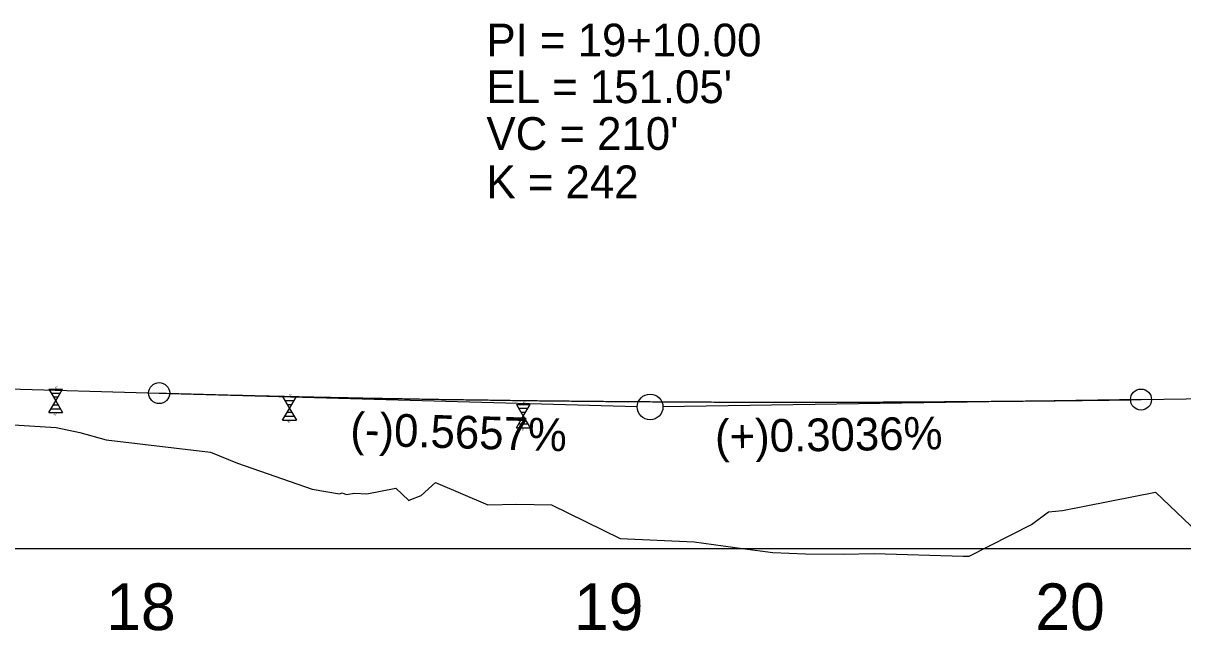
# Model space of a CAD drawing. Extents: x 573468 to 580768, y -57414 to -51768.
# Drawn here: x 574547.3 to 574795.4, y -53423 to -53293 of the extents above; entities that cross this region are included whole.
import ezdxf

# ---------------------------------------------------------------- set-up
doc = ezdxf.new("R2010")
doc.units = 0
for name, color, linetype in [('Exist Profile Cell', 7, 'Continuous'), ('Exist Vertical Profile Ground Line', 7, 'Continuous'), ('Exist Vertical Profile Horizontal Axis Label Major', 7, 'Continuous'), ('Pattern 2', 7, 'Continuous'), ('Prop Vertical Profile Curve Label', 7, 'Continuous'), ('Prop Vertical Profile Grade', 7, 'Continuous'), ('Prop Vertical Profile Grade Label', 7, 'Continuous'), ('Prop VPI Label', 7, 'Continuous')]:
    doc.layers.add(name, color=color, linetype=linetype)

msp = doc.modelspace()

# ---------------------------------------------------------------- linework, layer by layer
at = {"layer": 'Exist Profile Cell'}
msp.add_line((573502.62, -53405.32), (576177.52, -53405.32), dxfattribs=at)
at = {"layer": 'Exist Vertical Profile Ground Line'}
msp.add_lwpolyline([(574531.52, -53378.06), (574554.39, -53379.46), (574559.46, -53380.53), (574565.08, -53382.11), (574587.44, -53384.78), (574593.19, -53387.09), (574609.15, -53392.68), (574615.02, -53393.64), (574615.59, -53393.47), (574616.45, -53393.81), (574618.21, -53393.48), (574620.85, -53393.66), (574627.02, -53392.48), (574629.8, -53395.11), (574630.24, -53394.84), (574632.47, -53394.03), (574635.5, -53391.2), (574646.72, -53396.01), (574652.93, -53395.84), (574660.31, -53396.04), (574675.02, -53403.22), (574690.88, -53403.93), (574701.16, -53405.32), (574707.66, -53406.18), (574714.67, -53406.52), (574722.69, -53406.53), (574729.36, -53406.39), (574748.38, -53406.97), (574749.67, -53406.96), (574763.03, -53400.24), (574766.62, -53397.54), (574769.61, -53397.2), (574789.52, -53393.31), (574798.57, -53401.9)], dxfattribs=at)
at = {"layer": 'Pattern 2'}
for p, q in [((574552.84, -53371.27), (574555.77, -53371.27)), ((574552.84, -53371.27), (574554.31, -53373.77)), ((574553.33, -53372.1), (574555.29, -53372.1)), ((574553.82, -53372.94), (574554.8, -53372.94)), ((574554.31, -53373.77), (574555.77, -53371.27)), ((574602.84, -53372.87), (574605.77, -53372.87)), ((574602.84, -53372.87), (574604.31, -53375.37)), ((574603.33, -53373.7), (574605.29, -53373.7)), ((574604.31, -53375.37), (574605.77, -53372.87)), ((574552.84, -53376.27), (574554.31, -53373.77)), ((574553.33, -53375.44), (574555.29, -53375.44)), ((574553.82, -53374.6), (574554.8, -53374.6)), ((574554.31, -53373.77), (574555.77, -53376.27)), ((574602.84, -53377.87), (574604.31, -53375.37)), ((574603.82, -53374.54), (574604.8, -53374.54)), ((574603.82, -53376.2), (574604.8, -53376.2)), ((574604.31, -53375.37), (574605.77, -53377.87)), ((574652.84, -53374.52), (574655.77, -53374.52)), ((574652.84, -53374.52), (574654.31, -53377.02)), ((574653.33, -53375.35), (574655.29, -53375.35)), ((574653.82, -53376.19), (574654.8, -53376.19)), ((574654.31, -53377.02), (574655.77, -53374.52)), ((574552.84, -53376.27), (574555.77, -53376.27)), ((574602.84, -53377.87), (574605.77, -53377.87)), ((574603.33, -53377.04), (574605.29, -53377.04)), ((574652.84, -53379.52), (574654.31, -53377.02)), ((574653.33, -53378.69), (574655.29, -53378.69)), ((574653.82, -53377.85), (574654.8, -53377.85)), ((574654.31, -53377.02), (574655.77, -53379.52)), ((574652.84, -53379.52), (574655.77, -53379.52))]:
    msp.add_line(p, q, dxfattribs=at)
at = {"layer": 'Prop Vertical Profile Curve Label'}
for centre in [(574576.43, -53372.11), (574786.43, -53373.49)]:
    msp.add_circle(centre, 2.25, dxfattribs=at)
at = {"layer": 'Prop Vertical Profile Grade'}
for p, q in [((573747.58, -53348.67), (574576.43, -53372.11)), ((574786.43, -53373.49), (574804.31, -53373.22))]:
    msp.add_line(p, q, dxfattribs=at)
msp.add_spline([(574576.43, -53372.11), (574580.63, -53372.23), (574584.83, -53372.34), (574589.03, -53372.45), (574593.23, -53372.56), (574597.43, -53372.66), (574601.63, -53372.76), (574605.83, -53372.85), (574610.03, -53372.95), (574614.23, -53373.03), (574618.43, -53373.12), (574622.63, -53373.2), (574626.83, -53373.27), (574631.03, -53373.35), (574635.23, -53373.42), (574639.43, -53373.48), (574643.63, -53373.54), (574647.83, -53373.6), (574652.03, -53373.66), (574656.23, -53373.71), (574660.43, -53373.76), (574664.63, -53373.8), (574668.83, -53373.84), (574673.03, -53373.88), (574677.23, -53373.91), (574681.43, -53373.94), (574685.63, -53373.97), (574689.83, -53373.99), (574694.03, -53374.01), (574698.23, -53374.02), (574702.43, -53374.03), (574706.63, -53374.04), (574710.83, -53374.04), (574715.03, -53374.04), (574719.23, -53374.04), (574723.43, -53374.03), (574727.63, -53374.02), (574731.83, -53374.01), (574736.03, -53373.99), (574740.23, -53373.97), (574744.43, -53373.94), (574748.63, -53373.91), (574752.83, -53373.88), (574757.03, -53373.84), (574761.23, -53373.8), (574765.43, -53373.76), (574769.63, -53373.71), (574773.83, -53373.66), (574778.03, -53373.61), (574782.23, -53373.55), (574786.43, -53373.49)], degree=3, dxfattribs=at)
at = {"layer": 'Prop VPI Label'}
for p, q in [((574576.43, -53372.11), (574678.68, -53375)), ((574786.43, -53373.49), (574684.18, -53375.04))]:
    msp.add_line(p, q, dxfattribs=at)
msp.add_circle((574681.43, -53375.08), 2.75, dxfattribs=at)

# ---------------------------------------------------------------- texts
at = {"layer": 'Exist Vertical Profile Horizontal Axis Label Major'}
for s, p in [('18', (574565.09, -53422.82)), ('19', (574665.14, -53422.82)), ('20', (574763.81, -53422.82))]:
    msp.add_text(s, height=10, dxfattribs=at).set_placement(p)
at = {"layer": 'Pattern 2'}
for s, p in [('6"', (574554.2, -53371.17)), ('6"', (574604.2, -53372.77)), ('6"', (574654.2, -53374.42)), ('-6"', (574553.73, -53376.87)), ('-6"', (574603.73, -53378.47)), ('-6"', (574653.73, -53380.12))]:
    msp.add_text(s, height=0.5, rotation=360, dxfattribs=at).set_placement(p)
at = {"layer": 'Prop Vertical Profile Curve Label'}
for s, p in [("VC = 210'", (574646.43, -53320.08)), ('K = 242', (574646.43, -53330.42))]:
    msp.add_text(s, height=7, dxfattribs=at).set_placement(p)
at = {"layer": 'Prop Vertical Profile Grade Label'}
for s, rotation, p in [('(-)0.5657%', 358.3799, (574617.24, -53383.27)), ('(+)0.3036%', 0.8697, (574695.36, -53384.87))]:
    msp.add_text(s, height=7, rotation=rotation, dxfattribs=at).set_placement(p)
at = {"layer": 'Prop VPI Label'}
for s, p in [('PI = 19+10.00', (574646.43, -53300.08)), ("EL = 151.05'", (574646.43, -53310.08))]:
    msp.add_text(s, height=7, dxfattribs=at).set_placement(p)

doc.saveas('drawing.dxf')
